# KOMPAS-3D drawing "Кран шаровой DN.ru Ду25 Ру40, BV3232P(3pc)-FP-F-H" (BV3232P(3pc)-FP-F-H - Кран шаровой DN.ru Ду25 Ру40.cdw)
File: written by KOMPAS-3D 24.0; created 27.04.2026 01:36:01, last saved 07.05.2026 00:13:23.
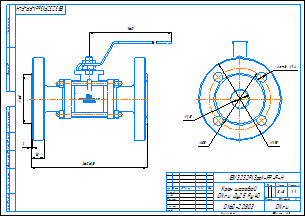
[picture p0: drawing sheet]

Document properties: Автор: Максим; Форматы листов документа: A3; Полное имя файла: BVxxP(3pc)-FP-F-H - Кран шаровой DN.ru Ду25 Ру40.cdw; Масса: 3.43; Наименование: Кран шаровой DN.ru Ду25 Ру40; Количество листов документа: 1; Примечание: D160-22803

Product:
- Body: Тело 1  | qty 1
    Масса: 3.757809
- Part/product: Кран шаровой DN.ru Ду25 Ру40  | designation BV3232P(3pc)-FP-F-H
    Масса: 3.43
    Раздел спецификации: Прочие изделия
    Форматы листов документа: A3
    Примечание: D160-22803

Views: Вид 1, Вид:2, Проекционный вид 2, Вид:1
Referenced files in D:\Rabota ebanaya\Апрель\BVxxP(3pc)-FP-F-H Кран шаровой Ду15-100\Исходники\DN25\: BVxxP(3pc)-FP-F-H - Кран шаровой DN.ru Ду25 Ру40.m3d, BVxxP(3pc)-FP-F-H - Кран шаровой DN.ru Ду25 Ру40.cdw
Referenced files in D:\Rabota ebanaya\Апрель\BV3232P(3pc)-FP-F-H Кран шаровой Ду15-100\Исходники\DN25\: BV3232P(3pc)-FP-F-H - Кран шаровой DN.ru Ду25 Ру40.m3d
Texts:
  Линейный размер
  BV3232P(3pc)-FP-F-H
  Диаметральный размер
  Кран шаровой
  DN.ru Ду25 Ру40
  Кран шаровой DN.ru Ду25 Ру40
  BV3232P(3pc)-FP-F-H Кран шаровой DN.ru Ду25 Ру40
Dimensions and other numbers on the sheet: 0; 3; 2; 4; 160±1,5; 18; 68; 25; 115; 85; 4 отв.; 14; 1:1; 1; 3,43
